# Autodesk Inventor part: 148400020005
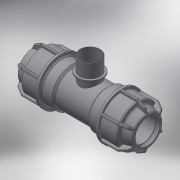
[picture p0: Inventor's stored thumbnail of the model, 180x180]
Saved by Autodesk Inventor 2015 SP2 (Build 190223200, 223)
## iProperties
Created: 2017-08
Part Number: 148400020005
Material: Generic
Description: PLASSON L.14 TEE MALE ADAPTOR (SILVER) 20-1/2"-20
Document SubType Name: Modeling
Designer: KIM
Density: 1 g/cm^3
Appearance: Default
Author: KIM
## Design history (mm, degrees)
derived "148400.ipt"
feature "Solid1::148400.ipt"
feature "Solid2::148400.ipt"
tag "TaggingFeature1"
body "Solid1"
body "Solid2"
other parameters: "d2" = 44, "d4" = 15 deg, "d5" = 29.04, "d6" = 9.5832, "d10" = 42, "d16" = 20.4, "d17" = 2.2, "d22" = 32, "d24" = 2.2, "d25" = 37.8, "d26" = 31.5, "d27" = 2.2, "d28" = 135 deg, "d29" = 1.32, "d31" = 1, "d46" = 150 deg, "d49" = 2.1, "d50" = 0, "d58" = 0.6, "d61" = 360 deg, "d63" = 18, "d64" = 56.5, "d80" = 28.8, "d81" = 1.6, "d84" = 2.2, "d94" = 44, "d96" = 20.955, "d108" = 0.6, "d111" = 0, "d113" = 16, "d114" = 25.146, "d115" = 17, "d116" = 1.7, "d117" = 20.955, "R_" = 20.955, "E_" = 42, "H_" = 113, "l_" = 44, "l_2" = 17, "A_" = 44
